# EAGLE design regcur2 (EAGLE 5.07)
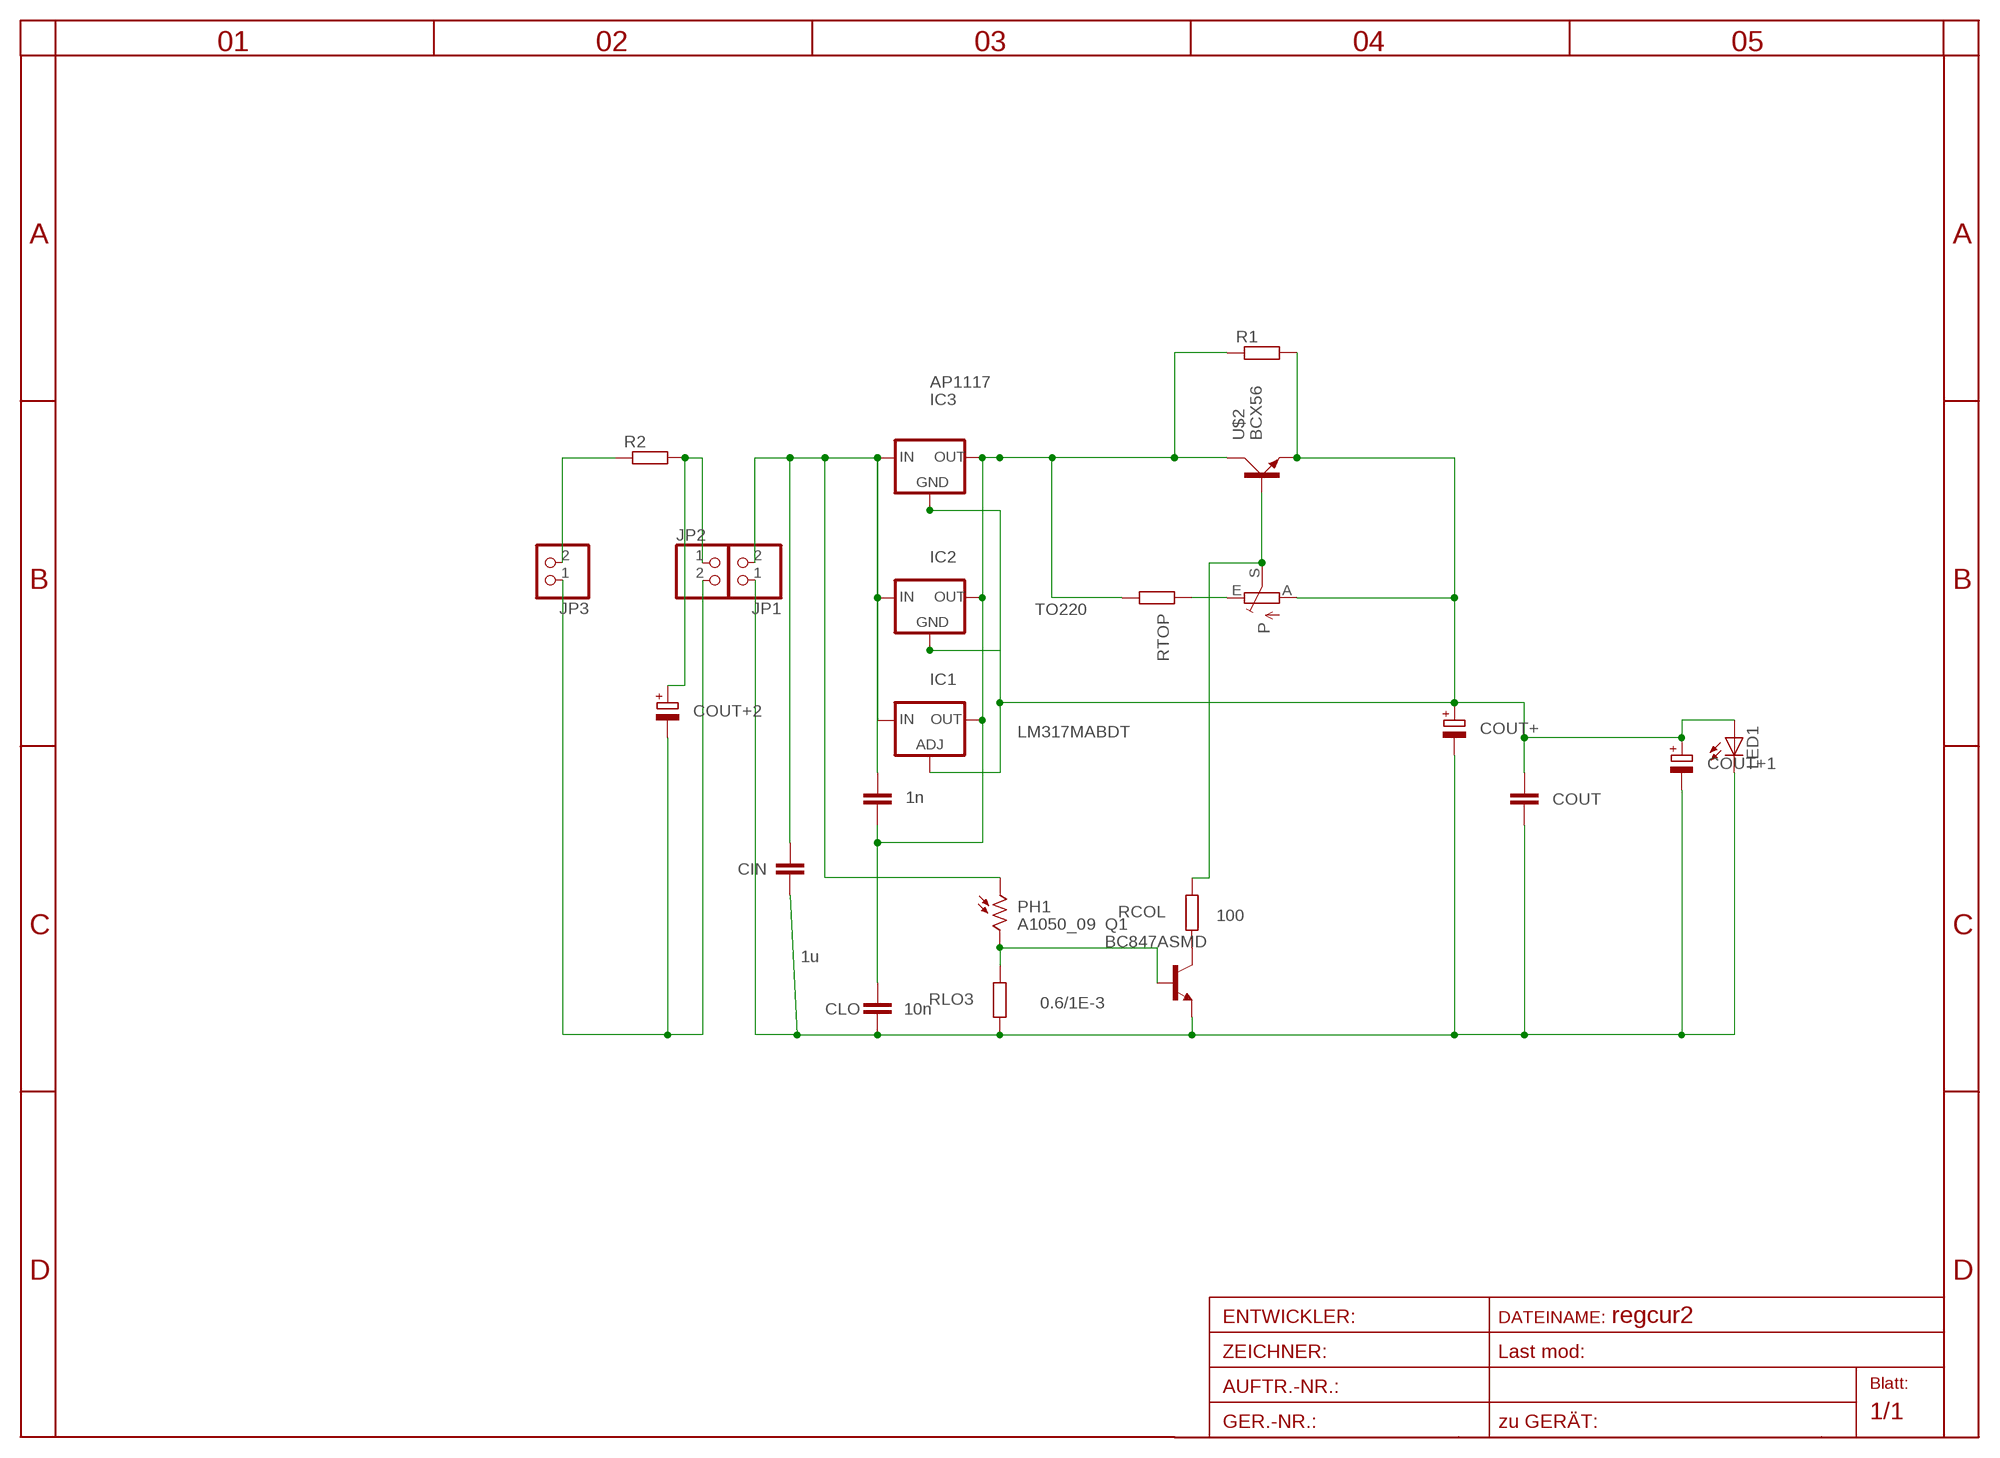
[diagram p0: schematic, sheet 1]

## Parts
CHI  1n  C-EUC0805  [C0805]
CIN  1u  C-EUC1206  [C1206]
CLO  10n  C-EUC0805  [C0805]
COUT  C-EUC1206  [C1206]
COUT+  CPOL-EUE7.5-16  [E7,5-16]
COUT+1  CPOL-EUE7.5-16  [E7,5-16]
COUT+2  CPOL-EUE3.5-8  [E3,5-8]
IC1  LM317MABDT  [DPACK]
IC2  TO220  78XXS  [78XXS]
IC3  AP1117  [SOT223]
JP1  PINHD-1X2STR  [1X02]
JP2  PINHD-1X2STR  [1X02]
JP3  PINHD-1X2STR  [1X02]
LED1  LED1W1MM6  [1W1MM6]
P  TRIM_EU-RAND160  [RANDL]
PH1  A1050_09  [T0-46-A10XX]
Q1  BC847ASMD  [SOT23]
R1  R-EU_R1210  [R1210]
R2  R-EU_R2010  [R2010]
RCOL  100  R-EU_R0805  [R0805]
RLO3  0.6/1E-3  R-EU_R0805  [R0805]
RTOP  R-EU_R0805  [R0805]
U$2  BCX56  [SOT223]

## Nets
GND: CIN.2 CLO.2 COUT+1.- COUT+.- COUT.2 JP1.1 LED1.C Q1.2(E) RLO3.1
IN: CHI.1 CIN.1 IC1.3(IN) IC2.IN IC3.3(IN) JP1.2 PH1.1
N$1: JP3.2 R2.1
N$2: COUT+2.+ JP2.1 R2.2
N$3: Q1.3(C) RCOL.1
N$4: P.E RTOP.1
N$5: P.S RCOL.2 U$2.1(B)
N$6: PH1.2 Q1.1(B) RLO3.2
N$7: COUT+2.- JP2.2 JP3.1
OUT: COUT+1.+ COUT+.+ COUT.1 IC1.1(ADJ) IC2.GND IC3.1(GND) LED1.A P.A R1.2 U$2.3(E)
OUT1: CHI.2 CLO.1 IC1.4(OUT) IC2.OUT IC3.2(OUT) IC3.4(TAB) R1.1 RTOP.2 U$2.2(C)

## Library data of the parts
CHI CIN CLO COUT = rcl:C-EU: CAPACITOR, European symbol
COUT+ COUT+1 COUT+2 = rcl:CPOL-EU: POLARIZED CAPACITOR, European symbol
IC1 = v-reg:LM317?*: 500 mA Adjustable Output Positive Voltage Regulator Source: http://www.onsemi.co.jp .. LM317M-D.PDF
IC2 = v-reg:78XXS: VOLTAGE REGULATOR
IC3 = v-reg:AP1117
JP1-JP3 = pinhead:PINHD-1X2: PIN HEADER
LED1 = led:LED: LED
P = pot:TRIM_EU-: POTENTIOMETER
PH1 = photo-elements:A10: Sensor Robust Light Sensing Applications
Q1 = transistor-npn:BC847*: NPN Transistor
R1 R2 RCOL RLO3 RTOP = rcl:R-EU_: RESISTOR, European symbol
U$2 = transistor-power:BCX56

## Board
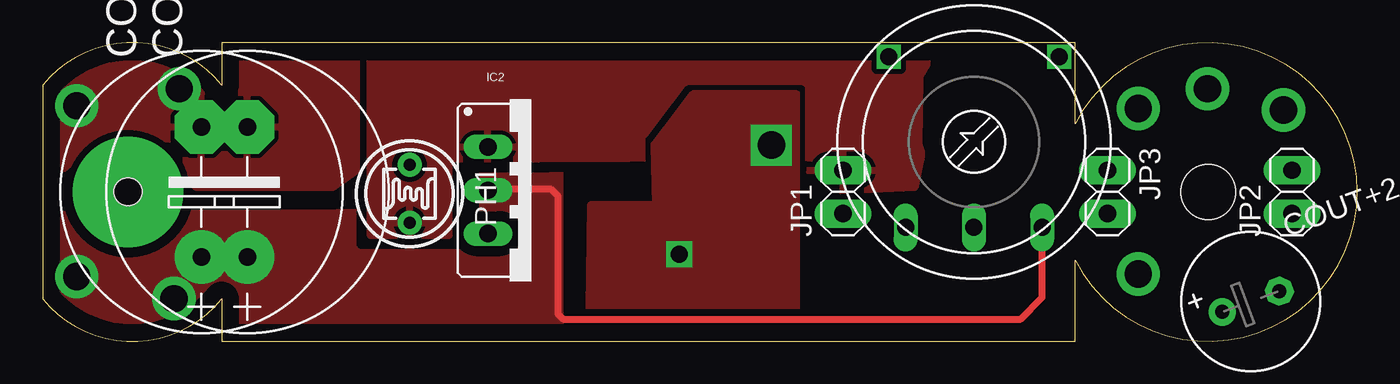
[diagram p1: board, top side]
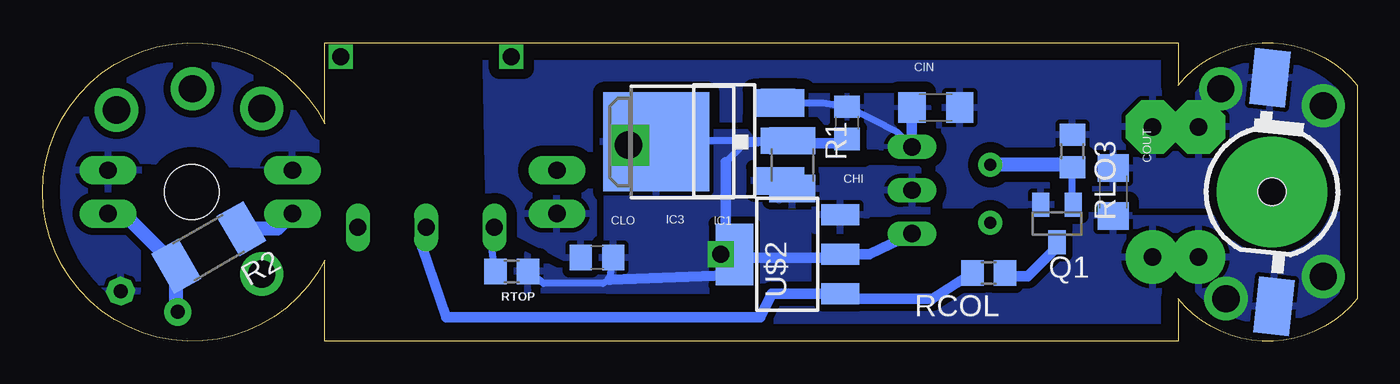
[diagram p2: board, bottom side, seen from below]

Size 77.03 x 17.5 mm. Coordinates in mm from the lower left corner, seen from the top.
Outline: 10.5,15 arc102 0,15
Outline: 0,2.5 arc102 10.5,2.5
Outline: 10.5,15 10.5,17.5 60.5,17.5 60.5,12.75 arc-306 60.5,4.75 60.5,0 10.5,0 10.5,2.5
Outline: 10.5,15 arc102 0,15
Outline: 0,15 0,2.5
Outline: 0,2.5 arc102 10.5,2.5
Copper layers (1*16): Top 0.035mm / dielectric 1.5mm / Bottom 0.035mm
Design rules "default *": minimum track width 10mil, minimum drill 20mil, track to track 8mil, track to pad 8mil, pad to pad 8mil, via to via 8mil, smd to smd 8mil, copper to edge 40mil, drill to drill 8mil, minimum pad ring 8mil, minimum via ring 8mil, stop-mask expansion 8mil, vias tented up to drill 0mil, thermal gap 10mil
Holes 3.2 mm at 68.3,8.75

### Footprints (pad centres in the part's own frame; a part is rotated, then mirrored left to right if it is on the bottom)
C0805 = smd 1.3 x 1.5: 1 -0.95,0; 2 0.95,0
C1206 = smd 1.6 x 1.8: 1 -1.4,0; 2 1.4,0
E7,5-16 = drill 1.016 pad 3.15 round: + -3.81,0 | drill 1.016 pad 3.15 octagon: - 3.81,0
E3,5-8 = drill 0.813 pad 1.6 round: + -1.778,0 | drill 0.813 pad 1.6 octagon: - 1.778,0
DPACK = smd 1.6 x 3: 1 -2.28,-4.8; 3 2.28,-4.8 | smd 5.8 x 6.2: 4 0,2.38
78XXS = drill 1.016 long: GND 0,-2.54; IN -2.54,-2.54; OUT 2.54,-2.54
SOT223 = smd 1.5 x 2: 1 -2.3,-3.15; 2 0,-3.15; 3 2.3,-3.15 | smd 3.8 x 2: 4 0,3.15
1X02 = drill 1.016 pad 1.676 long: 1 -1.27,0; 2 1.27,0
1W1MM6 = smd 3.3 x 2.1: A -6.65,-0.82; C 6.65,0.82 | drill 1.6 pad 6.452 round: P$1 0,0 | hole 1.6: 0,0
RANDL = drill 1 long: A -4,5; E 4,5; S 0,5 | drill 1 square: P$1 -5,-5; P$2 5,-5
T0-46-A10XX = drill 0.7 pad 1.4 round: 1 -1.7,0; 2 1.7,0
SOT23 = smd 1 x 1.4: 1 -0.95,-1.1; 2 0.95,-1.1; 3 0,1.1
R1210 = smd 1.6 x 2.7: 1 -1.4,0; 2 1.4,0
R2010 = smd 1.8 x 2.7: 1 -2.2,0; 2 2.2,0
R0805 = smd 1.3 x 1.5: 1 -0.95,0; 2 0.95,0
SOT223' = smd 1.219 x 2.235: 1 -2.311,-3.099; 2 0,-3.099; 3 2.311,-3.099 | smd 3.6 x 2.2: 4 0,3.099

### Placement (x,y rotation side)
CHI  29.9,12.8 270 bottom
CIN  24.7,13.7 0 bottom
CLO  44.55,4.9 180 bottom
COUT  14.3,8.75 90 bottom
COUT+  12,8.75 90 top
COUT+1  9.3,8.75 90 top
COUT+2  70.79,2.33 20 top
IC1  38.7,11.68 90 bottom
IC2  28.63,8.85 270 top
IC3  37.1,11.75 90 bottom
JP1  46.9,8.75 90 top
JP2  73.2,8.75 90 top
JP3  62.4,8.75 270 top
LED1  5,8.75 84 bottom
P  54.57,11.68 180 top
PH1  21.5,8.65 90 top
Q1  17.6,6.9 180 bottom
R1  33.1,10.35 270 bottom
R2  67.3,5.5 210 bottom
RCOL  21.6,4 180 bottom
RLO3  16.7,11.15 270 bottom
RTOP  49.55,4.1 0 bottom
U$2  BCX56  [SOT223']  33.4,5.1 90 bottom

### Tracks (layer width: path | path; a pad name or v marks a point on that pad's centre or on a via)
GND  (via drill 1.6 pad 2.54)
  other vias: 8,14.8 2,13.8
  pour Bottom (isolate 0.61, rank 2): 0,15.5 arc-92 11,15 11,17.5 51.1,17.6 50.9,7.2 44.7,4 44.8,13.1 35.1,13 32,13.55 31,13.5 26.3,13.5 24.4,12.2 24.4,11.2 24.5,10.5 24.9,8 0.4,8
  pour Top (isolate 0.406, rank 3): 0.5,15 arc-78 10,15 10,13.5 11.5,13.5 11.5,16.6 18.4,16.6 18.4,10 17,9 9,9 6,12 3.5,12 0.5,9.5
IN
  Bottom 0.406: IC1.3 31.31,13.96 CHI.1 26.95,12.25 IC2.IN
  Bottom 0.61: CIN.1 IC2.IN
  pour Top (isolate 0.305, rank 2): 52,16.57 51.4,15.5 51.34,11.5 51.5,11 51.1,9 44.9,8.7 45,10.75 23.8,10.65 23.8,6.2 19.2,6.2 19.2,16.5
  pour Bottom (isolate 0.406): 25.6,14.4 35.2,14.4 35.2,13.3 31.6,13.3 30,11.4 28,11.4 27.6,11 25,10.9 25.1,14.2
N$1
  Bottom 0.813: R2.1 63.28,6.6 JP3.2
N$2
  Bottom 0.813: JP2.1 72.29,7.48 R2.2 69.21,1.81 COUT+2.+
N$3
  Bottom 0.406: Q1.3 17.6,5.5 | 20.45,3.8 RCOL.1
  Bottom 0.61: 17.6,5.5 19.3,3.8 20.45,3.8
N$4
  Bottom 0.406: P.E 50.72,5.58 50.6,4.6 50.7,4.1 RTOP.1
N$5
  Bottom 0.406: 30.01,2.5 U$2.1 | 54.8,5.5 54.8,6.45 P.S
  Bottom 0.61: RCOL.2 24.9,2.5 30.01,2.5 | U$2.1 34.31,2.79 35,1.4 53.4,1.4 54.8,5.5
N$6
  Bottom 0.406: 16.85,10.35 RLO3.2 16.7,8.05 Q1.1
  Bottom 0.813: 16.85,10.35 PH1.2
N$7
  pour Bottom (isolate 0.406): 61,10.2 61,13.4 61.4,13.8 67.5,17.7 arc-133 74.2,3 71.5,1.3 71.4,10.6
N$14  (via drill 1.6 pad 2.54)
  other vias: 72.7,13.55
N$15  (via drill 1.6 pad 2.54)
  other vias: 68.25,14.8
N$16  (via drill 1.6 pad 2.54)
  other vias: 64.2,13.65
OUT  (via drill 1.6 pad 2.54)
  Top 0.406: P.A 58.57,2.57 57.3,1.3 30.5,1.3 30.2,1.6 30.2,8.5 29.8,8.9 26.14,8.9 IC2.GND
  Bottom 0.61: R1.2 33.6,9.4 IC1.1 IC3.1
  other vias: 2,3.8 7.7,2.5
  pour Bottom (isolate 0.406, rank 3): 44.2,6.2 44,4.2 43.8,0.5 0.4,0.5 0.4,7.4 17.1,7.4 17,6.2
  pour Top (isolate 0.61, rank 4, no thermals): 30.3,0 10.5,0 10.5,1.5 arc-67 0,1.5 0,7.5 25.8,7.6 25.8,10.4 30.3,10.4
  pour Bottom (isolate 0.406, rank 3): 25,9.3 25.8,10.1 28.6,10.1 28.7,10 34.5,10 35.4,9.9 35.3,8.1 35.2,8 31.9,8 31.8,7.7 31.8,6.5 29.6,6.5 28.6,7.5 25.2,7.5
OUT1  (via drill 1, 1.6)
  Bottom 0.406: IC3.2 IC3.4 | IC3.2 35.95,11.55 37,10.5 | 36.3,4.9 36.5,5.1 | 36.5,5.1 36.85,5.45 37,5.6 | U$2.2 30.5,4.9 | 30.7,11.6 CHI.2 | 32,11.6 33.9,11.6 IC3.2 | RTOP.2 47.7,3.4 44.2,3.4 43.8,3.6 CLO.1 | 36.5,5.1 36.1,3.9
  Bottom 0.61: U$2.2 28.6,5.1 IC2.OUT | 37,5.6 37,10.5 | 30.5,4.9 36.3,4.9 | 32,11.6 30.7,11.6 | 36.1,3.9 43.8,3.6 | 33.9,11.6 33.2,11.6 R1.1 | v37.3,5.1 37.2,5.1 36.85,5.45
  other vias: 42.7,11.5
  pour Top (isolate 0.406): 32.1,8 32,1.9 44.2,1.9 44.2,14.5 38.1,14.5 35.8,11.5 35.9,8
  pour Bottom (isolate 0.406, rank 3): 32.2,8 32.2,2.9 49.9,3 44.1,14.5 37.4,14.2 35,11.2 35.1,8
VPROT  (via drill 1.6 pad 2.54)
  other vias: 64.2,3.95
